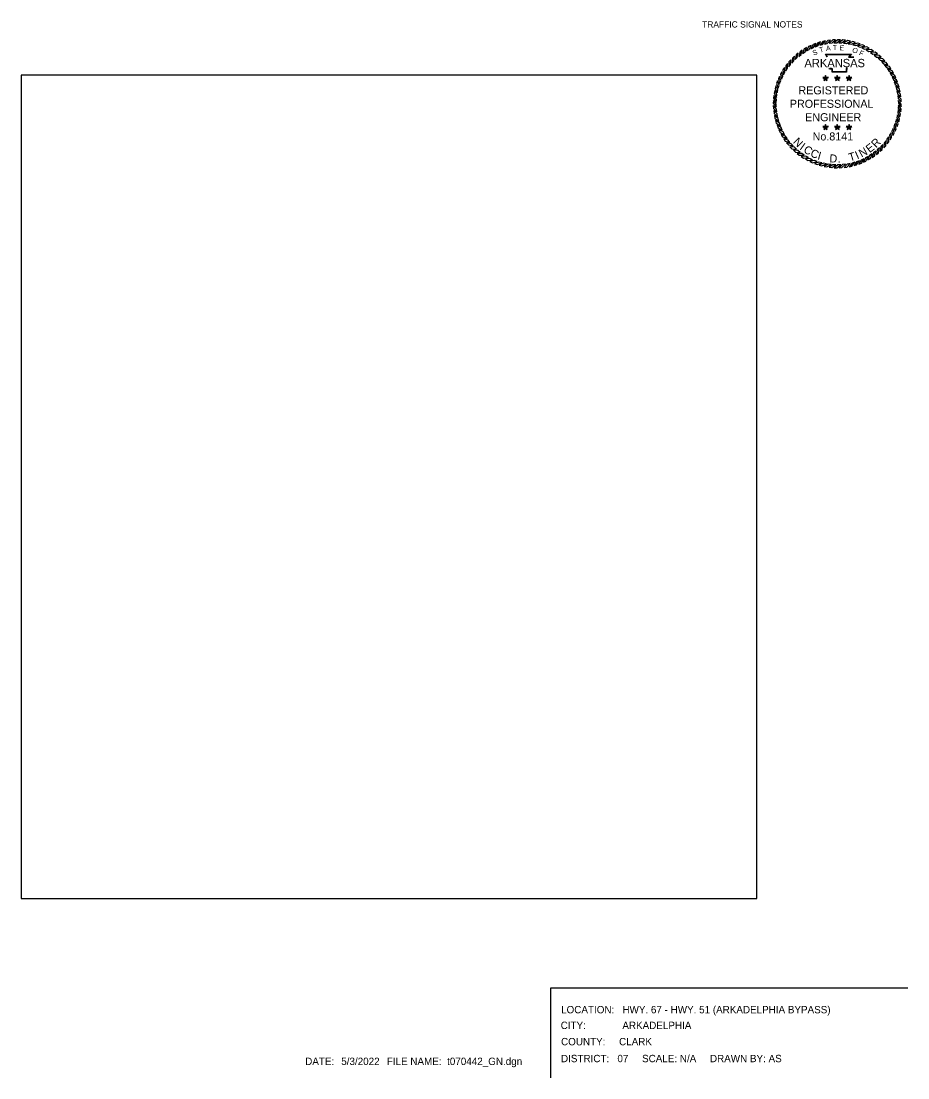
# Model space of a CAD drawing. Extents: x 418532 to 419834, y -565899 to -565283.
# Drawn here: x 419329 to 419834, y -565899 to -565297 of the extents above; entities that cross this region are included whole.
import ezdxf

# ---------------------------------------------------------------- set-up
doc = ezdxf.new("R2010")
doc.units = 0
for name, color, linetype in [('G-ANNO-SYMB', 7, 'Continuous'), ('G-ANNO-TEXT', 7, 'Continuous'), ('Level 10', 7, 'Continuous'), ('Level 57', 7, 'Continuous'), ('V-SIGNAL-LOOP', 7, 'Continuous')]:
    doc.layers.add(name, color=color, linetype=linetype)

msp = doc.modelspace()

# ---------------------------------------------------------------- linework, layer by layer
at = {"layer": 'G-ANNO-SYMB'}
for points in [[(419790.06, -565307.38), (419788.51, -565307.58), (419786.6, -565309.63), (419788.27, -565309.31)], [(419792.92, -565307.19), (419791.35, -565307.27), (419789.29, -565309.15), (419790.98, -565308.97)], [(419795.78, -565307.22), (419794.22, -565307.17), (419792.01, -565308.89), (419793.71, -565308.84)], [(419798.64, -565307.47), (419797.08, -565307.3), (419794.75, -565308.85), (419796.44, -565308.93)], [(419774.02, -565313.1), (419772.73, -565313.99), (419771.96, -565316.68), (419773.3, -565315.64)], [(419776.48, -565311.63), (419775.12, -565312.42), (419774.14, -565315.03), (419775.56, -565314.1)], [(419779.05, -565310.36), (419777.63, -565311.03), (419776.45, -565313.57), (419777.93, -565312.75)], [(419781.7, -565309.29), (419780.24, -565309.85), (419778.86, -565312.29), (419780.41, -565311.59)], [(419784.44, -565308.44), (419782.93, -565308.88), (419781.37, -565311.2), (419782.96, -565310.62)], [(419787.23, -565307.8), (419785.69, -565308.12), (419783.95, -565310.31), (419785.59, -565309.86)], [(419801.46, -565307.95), (419799.92, -565307.66), (419797.47, -565309.02), (419799.16, -565309.23)], [(419804.24, -565308.65), (419802.72, -565308.24), (419800.18, -565309.4), (419801.84, -565309.74)], [(419806.95, -565309.56), (419805.48, -565309.04), (419802.85, -565309.99), (419804.48, -565310.46)], [(419809.59, -565310.69), (419808.16, -565310.05), (419805.46, -565310.79), (419807.05, -565311.39)], [(419812.12, -565312.01), (419810.75, -565311.26), (419808, -565311.8), (419809.54, -565312.52)], [(419814.55, -565313.54), (419813.24, -565312.68), (419810.46, -565313), (419811.93, -565313.84)], [(419767.44, -565318.6), (419766.39, -565319.77), (419766.27, -565322.56), (419767.33, -565321.24)], [(419769.49, -565316.6), (419768.35, -565317.68), (419768.01, -565320.45), (419769.17, -565319.22)], [(419771.69, -565314.76), (419770.47, -565315.75), (419769.91, -565318.49), (419771.16, -565317.35)], [(419816.85, -565315.25), (419815.61, -565314.29), (419812.81, -565314.39), (419814.22, -565315.34)], [(419819.01, -565317.13), (419817.84, -565316.08), (419815.05, -565315.95), (419816.37, -565317.01)], [(419821.01, -565319.18), (419819.93, -565318.03), (419817.16, -565317.69), (419818.39, -565318.85)], [(419822.85, -565321.37), (419821.86, -565320.15), (419819.12, -565319.59), (419820.26, -565320.85)], [(419762.33, -565325.49), (419761.58, -565326.86), (419762.11, -565329.61), (419762.83, -565328.07)], [(419763.85, -565323.06), (419763, -565324.37), (419763.31, -565327.15), (419764.15, -565325.68)], [(419765.56, -565320.76), (419764.6, -565322), (419764.7, -565324.8), (419765.65, -565323.39)], [(419824.51, -565323.71), (419823.62, -565322.41), (419820.93, -565321.64), (419821.97, -565322.98)], [(419825.98, -565326.17), (419825.19, -565324.81), (419822.58, -565323.83), (419823.51, -565325.24)], [(419759.88, -565330.66), (419759.35, -565332.13), (419760.31, -565334.76), (419760.78, -565333.13)], [(419761, -565328.02), (419760.36, -565329.45), (419761.11, -565332.15), (419761.71, -565330.56)], [(419787.29, -565329.12), (419786.92, -565328.61), (419785.71, -565328.61), (419786.69, -565329.32)], [(419787.29, -565329.12), (419786.69, -565329.32), (419786.31, -565330.47), (419787.29, -565329.76)], [(419787.29, -565329.12), (419787.67, -565328.61), (419787.29, -565327.45), (419786.92, -565328.61)], [(419787.29, -565329.12), (419787.9, -565329.32), (419788.88, -565328.61), (419787.67, -565328.61)], [(419787.29, -565329.12), (419787.29, -565329.76), (419788.27, -565330.47), (419787.9, -565329.32)], [(419793.96, -565329.12), (419793.59, -565328.61), (419792.38, -565328.61), (419793.36, -565329.32)], [(419793.96, -565329.12), (419793.36, -565329.32), (419792.98, -565330.47), (419793.96, -565329.76)], [(419793.96, -565329.12), (419794.34, -565328.61), (419793.96, -565327.45), (419793.59, -565328.61)], [(419793.96, -565329.12), (419794.57, -565329.32), (419795.55, -565328.61), (419794.34, -565328.61)], [(419793.96, -565329.12), (419793.96, -565329.76), (419794.94, -565330.47), (419794.57, -565329.32)], [(419800.63, -565329.12), (419800.26, -565328.61), (419799.05, -565328.61), (419800.03, -565329.32)], [(419800.63, -565329.12), (419800.03, -565329.32), (419799.65, -565330.47), (419800.63, -565329.76)], [(419800.63, -565329.12), (419801.01, -565328.61), (419800.63, -565327.45), (419800.26, -565328.61)], [(419800.63, -565329.12), (419801.24, -565329.32), (419802.22, -565328.61), (419801.01, -565328.61)], [(419800.63, -565329.12), (419800.63, -565329.76), (419801.61, -565330.47), (419801.24, -565329.32)], [(419827.25, -565328.73), (419826.58, -565327.31), (419824.04, -565326.13), (419824.86, -565327.62)], [(419828.32, -565331.39), (419827.76, -565329.92), (419825.32, -565328.55), (419826.02, -565330.09)], [(419829.17, -565334.12), (419828.73, -565332.62), (419826.41, -565331.05), (419826.99, -565332.65)], [(419758.27, -565336.15), (419757.98, -565337.69), (419759.33, -565340.14), (419759.54, -565338.45)], [(419758.97, -565333.37), (419758.56, -565334.89), (419759.72, -565337.43), (419760.06, -565335.77)], [(419829.81, -565336.91), (419829.49, -565335.38), (419827.3, -565333.64), (419827.75, -565335.27)], [(419830.23, -565339.75), (419830.03, -565338.19), (419827.98, -565336.28), (419828.3, -565337.95)], [(419757.53, -565341.83), (419757.49, -565343.39), (419759.21, -565345.6), (419759.16, -565343.9)], [(419757.79, -565338.97), (419757.62, -565340.53), (419759.16, -565342.86), (419759.24, -565341.17)], [(419830.42, -565342.6), (419830.34, -565341.04), (419828.46, -565338.98), (419828.64, -565340.66)], [(419830.39, -565345.47), (419830.44, -565343.9), (419828.72, -565341.7), (419828.77, -565343.39)], [(419757.5, -565344.69), (419757.58, -565346.26), (419759.47, -565348.32), (419759.28, -565346.63)], [(419757.7, -565347.55), (419757.9, -565349.1), (419759.94, -565351.01), (419759.62, -565349.34)], [(419829.66, -565351.14), (419829.95, -565349.6), (419828.59, -565347.16), (419828.38, -565348.84)], [(419830.14, -565348.32), (419830.31, -565346.76), (419828.76, -565344.43), (419828.68, -565346.12)], [(419758.11, -565350.38), (419758.44, -565351.92), (419760.63, -565353.66), (419760.18, -565352.02)], [(419758.75, -565353.17), (419759.2, -565354.68), (419761.51, -565356.24), (419760.94, -565354.65)], [(419787.29, -565357.05), (419787.67, -565356.54), (419787.29, -565355.38), (419786.92, -565356.54)], [(419793.96, -565357.05), (419794.34, -565356.54), (419793.96, -565355.38), (419793.59, -565356.54)], [(419800.63, -565357.05), (419801.01, -565356.54), (419800.63, -565355.38), (419800.26, -565356.54)], [(419826.92, -565359.27), (419827.56, -565357.84), (419826.82, -565355.15), (419826.22, -565356.73)], [(419828.05, -565356.64), (419828.57, -565355.16), (419827.62, -565352.53), (419827.15, -565354.16)], [(419828.96, -565353.92), (419829.37, -565352.41), (419828.21, -565349.86), (419827.87, -565351.52)], [(419759.61, -565355.91), (419760.17, -565357.37), (419762.6, -565358.75), (419761.9, -565357.2)], [(419760.68, -565358.56), (419761.35, -565359.98), (419763.88, -565361.16), (419763.07, -565359.68)], [(419761.95, -565361.13), (419762.73, -565362.49), (419765.35, -565363.47), (419764.42, -565362.05)], [(419787.29, -565357.05), (419786.92, -565356.54), (419785.71, -565356.54), (419786.69, -565357.25)], [(419787.29, -565357.05), (419786.69, -565357.25), (419786.31, -565358.4), (419787.29, -565357.69)], [(419787.29, -565357.05), (419787.9, -565357.25), (419788.88, -565356.54), (419787.67, -565356.54)], [(419787.29, -565357.05), (419787.29, -565357.69), (419788.27, -565358.4), (419787.9, -565357.25)], [(419793.96, -565357.05), (419793.59, -565356.54), (419792.38, -565356.54), (419793.36, -565357.25)], [(419793.96, -565357.05), (419793.36, -565357.25), (419792.98, -565358.4), (419793.96, -565357.69)], [(419793.96, -565357.05), (419794.57, -565357.25), (419795.55, -565356.54), (419794.34, -565356.54)], [(419793.96, -565357.05), (419793.96, -565357.69), (419794.94, -565358.4), (419794.57, -565357.25)], [(419800.63, -565357.05), (419800.26, -565356.54), (419799.05, -565356.54), (419800.03, -565357.25)], [(419800.63, -565357.05), (419800.03, -565357.25), (419799.65, -565358.4), (419800.63, -565357.69)], [(419800.63, -565357.05), (419801.24, -565357.25), (419802.22, -565356.54), (419801.01, -565356.54)], [(419800.63, -565357.05), (419800.63, -565357.69), (419801.61, -565358.4), (419801.24, -565357.25)], [(419824.07, -565364.23), (419824.93, -565362.92), (419824.61, -565360.14), (419823.77, -565361.62)], [(419825.6, -565361.81), (419826.35, -565360.43), (419825.81, -565357.69), (419825.09, -565359.22)], [(419763.42, -565363.59), (419764.31, -565364.88), (419766.99, -565365.65), (419765.95, -565364.31)], [(419765.08, -565365.92), (419766.06, -565367.14), (419768.8, -565367.7), (419767.66, -565366.45)], [(419818.43, -565370.69), (419819.58, -565369.62), (419819.92, -565366.84), (419818.76, -565368.08)], [(419820.48, -565368.69), (419821.53, -565367.53), (419821.66, -565364.73), (419820.6, -565366.06)], [(419822.36, -565366.53), (419823.32, -565365.29), (419823.22, -565362.5), (419822.27, -565363.9)], [(419766.92, -565368.12), (419767.99, -565369.26), (419770.77, -565369.6), (419769.53, -565368.44)], [(419768.92, -565370.17), (419770.08, -565371.22), (419772.88, -565371.34), (419771.55, -565370.28)], [(419771.08, -565372.05), (419772.32, -565373.01), (419775.11, -565372.91), (419773.71, -565371.96)], [(419773.38, -565373.76), (419774.69, -565374.61), (419777.47, -565374.3), (419775.99, -565373.46)], [(419808.88, -565376.93), (419810.3, -565376.26), (419811.48, -565373.73), (419809.99, -565374.54)], [(419811.44, -565375.66), (419812.8, -565374.88), (419813.78, -565372.26), (419812.37, -565373.19)], [(419813.9, -565374.19), (419815.2, -565373.3), (419815.97, -565370.62), (419814.63, -565371.66)], [(419816.24, -565372.53), (419817.46, -565371.55), (419818.02, -565368.81), (419816.76, -565369.95)], [(419775.8, -565375.28), (419777.18, -565376.03), (419779.92, -565375.5), (419778.39, -565374.78)], [(419778.34, -565376.61), (419779.77, -565377.25), (419782.46, -565376.5), (419780.88, -565375.9)], [(419780.97, -565377.73), (419782.45, -565378.26), (419785.08, -565377.3), (419783.45, -565376.83)], [(419783.69, -565378.64), (419785.2, -565379.05), (419787.75, -565377.89), (419786.09, -565377.55)], [(419786.47, -565379.34), (419788.01, -565379.63), (419790.45, -565378.28), (419788.77, -565378.07)], [(419789.29, -565379.82), (419790.85, -565379.99), (419793.18, -565378.45), (419791.49, -565378.37)], [(419792.14, -565380.08), (419793.71, -565380.12), (419795.91, -565378.4), (419794.22, -565378.45)], [(419795.01, -565380.11), (419796.57, -565380.03), (419798.63, -565378.14), (419796.95, -565378.33)], [(419797.86, -565379.91), (419799.42, -565379.71), (419801.33, -565377.67), (419799.66, -565377.99)], [(419800.7, -565379.5), (419802.23, -565379.17), (419803.97, -565376.98), (419802.34, -565377.43)], [(419803.49, -565378.86), (419804.99, -565378.41), (419806.56, -565376.1), (419804.96, -565376.67)], [(419806.22, -565378), (419807.69, -565377.44), (419809.06, -565375.01), (419807.52, -565375.71)]]:
    msp.add_lwpolyline(points, close=True, dxfattribs=at)
for points in [[(419788.12, -565317.17), (419787.27, -565315.33), (419801.98, -565315.32), (419800.75, -565316.87), (419801.75, -565316.86), (419802.59, -565316.84), (419803.42, -565316.94)], [(419788.33, -565317.08), (419787.63, -565315.57), (419801.5, -565315.56), (419800.26, -565317.11), (419801.75, -565317.09), (419802.58, -565317.08), (419803.4, -565317.17)], [(419799.66, -565323.34), (419799.41, -565323.54), (419799.33, -565323.85), (419799.25, -565324.61), (419799.25, -565325.63), (419791.03, -565325.63), (419791.03, -565324.26), (419791.03, -565323.95), (419790.7, -565323.85), (419789.53, -565323.85), (419789.32, -565323.53)], [(419799.52, -565323.16), (419799.21, -565323.41), (419799.1, -565323.8), (419799.01, -565324.6), (419799.01, -565325.4), (419791.27, -565325.4), (419791.27, -565324.26), (419791.27, -565323.78), (419790.73, -565323.62), (419789.66, -565323.62), (419789.52, -565323.4)]]:
    msp.add_lwpolyline(points, dxfattribs=at)
at = {"layer": 'Level 57'}
for points in [[(419630.59, -565847.55), (419630.59, -565898.75)], [(419834.17, -565847.55), (419630.59, -565847.55)], [(419630.59, -565847.55), (419630.59, -565898.5)]]:
    msp.add_lwpolyline(points, dxfattribs=at)
at = {"layer": 'V-SIGNAL-LOOP'}
msp.add_lwpolyline([(419328.85, -565796.6), (419748.13, -565796.6), (419748.13, -565327.42), (419328.85, -565327.42)], close=True, dxfattribs=at)

# ---------------------------------------------------------------- texts
at = {"layer": 'G-ANNO-SYMB'}
for s, height, rotation, p in [('S', 2.9, 19.77256, (419780.46, -565316.21)), ('T', 2.9, 16.90148, (419784.15, -565314.55)), ('A', 2.9, 8.67877, (419787.67, -565313.63)), ('T', 2.9, 1.47887, (419791.42, -565313.05)), ('E', 2.9, 356.67203, (419795.13, -565313.14)), ('O', 2.9, 341.2218, (419802.18, -565314.14)), ('F', 2.9, 335.36282, (419806.09, -565315.67)), ('N', 4.59, 315.26758, (419768.48, -565365.65)), ('I', 4.59, 324.21406, (419772.21, -565369.34)), ('C', 4.59, 328.68731, (419774.28, -565370.96)), ('E', 4.59, 37.64979, (419812.39, -565371.82)), ('R', 4.59, 45.47796, (419816.05, -565369.05)), ('C', 4.59, 336.51548, (419778.19, -565373.38)), ('I', 4.59, 344.34365, (419782.38, -565375.26)), ('D', 4.59, 356.64507, (419789.38, -565377)), ('T', 4.59, 16.77466, (419801.14, -565376.54)), ('I', 4.59, 24.23006, (419805.35, -565375.33)), ('N', 4.59, 28.7033, (419807.78, -565374.34)), ('.', 4.59, 4.84601, (419794.19, -565377.31))]:
    msp.add_text(s, height=height, rotation=rotation, dxfattribs=at).set_placement(p)
for s, height, p in [('ARKANSAS', 4.737, (419775.24, -565322.81)), ('REGISTERED', 4.585, (419771.8, -565338.27)), ('PROFESSIONAL', 4.5855, (419766.89, -565345.94)), ('ENGINEER', 4.585, (419775.62, -565353.61)), ('No.8141', 4.567, (419779.9, -565364.54))]:
    msp.add_text(s, height=height, dxfattribs=at).set_placement(p)
at = {"layer": 'G-ANNO-TEXT'}
msp.add_text('TRAFFIC SIGNAL NOTES', height=3.6, dxfattribs=at).set_placement((419716.91, -565300.21))
at = {"layer": 'Level 10'}
for s, p in [('LOCATION:   HWY. 67 - HWY. 51 (ARKADELPHIA BYPASS)', (419636.58, -565861.97)), ('CITY:', (419636.32, -565870.93)), (' ARKADELPHIA', (419669.92, -565870.93)), ('COUNTY:     CLARK', (419636.53, -565880.2)), ('DISTRICT:   07     SCALE: N/A     DRAWN BY: AS', (419636.51, -565889.83)), ('DATE:  ', (419490.73, -565891.43)), ('5/3/2022', (419511.28, -565891.43)), ('  FILE NAME: ', (419534.11, -565891.43)), ('t070442_GN.dgn', (419571.6, -565891.43))]:
    msp.add_text(s, height=4.2, rotation=360, dxfattribs=at).set_placement(p)

doc.saveas('drawing.dxf')
